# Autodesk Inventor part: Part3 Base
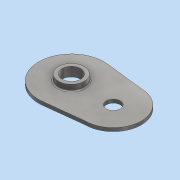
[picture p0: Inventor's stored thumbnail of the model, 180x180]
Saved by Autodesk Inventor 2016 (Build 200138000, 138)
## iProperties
Created: 2015-11
Part Number: Part3 Base
Material: Steel, Alloy
Document SubType Name: Modeling
Designer: SanPer86
Density: 7.73 g/cm^3
Appearance: Semi-Polished
Mass: 0.181321 g
Surface Area: 1.39666 cm^2
Volume: 0.0234568 cm^3
Author: SanPer86
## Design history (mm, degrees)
sketch "Sketch1"
  geometry: L1 (4.513, 3)-(0.378, 3.48); L2 (4.513, -2.996)-(0.576, -3.452); L3 (0.576, -3.452)-(0.378, -3.475); C1 r 0.75 at (4.5, 0); A1 r 3.5 centre (0, 0) between (0.429, 3.474) and (0.576, -3.452); A2 r 3 centre (4.5, 0) between (2.611, 2.331) and (4.477, -3); A3 r 3 centre (4.5, 0) between (4.513, 3) and (2.611, 2.331); A4 r 3 centre (4.5, 0) between (4.477, -3) and (4.513, 3); A5 r 3.5 centre (0, 0) between (2.611, 2.331) and (0.429, 3.474); A6 r 3.5 centre (0, 0) between (0.576, -3.452) and (2.611, 2.331); 1 further point
  constraints: 14 point on circle, 7 centre point, 6 end point, 2 coincident, 2 point on line
  dimensions: "d0" = 7 diameter of A1; "d1" = 6 diameter of A2; "d2" = 4.5 distance of A2.centre point (0, 0); "d3" = 1.5 diameter of C1
extrude "Extrusion1" new body sketch "Sketch1" distance "d5" = 0.375; taper "d6" = 0 deg
sketch "Sketch2"
  geometry: C1 r 1.375 at (0, 0); 1 further point
  constraints: 1 centre point, 1 coincident
  dimensions: "d7" = 2.75 diameter of C1
extrude "Extrusion2" join sketch "Sketch2" distance "d8" = 0.625; taper "d9" = 0 deg
sketch "Sketch3"
  geometry: C1 r 1 at (0, 0); 1 further point
  constraints: 1 centre point, 1 coincident
  dimensions: "d10" = 2 diameter of C1
extrude "Extrusion3" cut sketch "Sketch3" stored distance "d11" = 0.625; taper "d12" = 0 deg
fillet "Fillet1" dims "d13" = 0.125
body "Solid1"
